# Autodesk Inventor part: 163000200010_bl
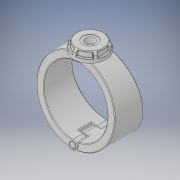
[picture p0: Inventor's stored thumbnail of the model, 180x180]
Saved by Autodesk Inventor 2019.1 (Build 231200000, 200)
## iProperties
Created: 2022-02
Part Number: 163000200010_bl
Material: Generic
Description: Plassadle Threaded 200x1''
Document SubType Name: Modeling
Designer: comp2
Density: 1 g/cm^3
Appearance: Default
Author: comp2
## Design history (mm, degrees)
derived "16300.ipt"
feature "Solid1::16300.ipt" dims "ScaleForDerivedMember" = 10
feature "Solid2::16300.ipt" dims "ScaleForDerivedMember" = 10
feature "Solid3::16300.ipt" dims "ScaleForDerivedMember" = 10
feature "Solid4::16300.ipt" dims "ScaleForDerivedMember" = 10
tag "TaggingFeature1"
body "Solid1"
body "Solid2"
body "Solid3"
body "Solid4"
other parameters: "d2" = 246 [user parameter], "d7" = 233.7 [user parameter], "d8" = 85 deg [user parameter], "d9" = 45 deg [user parameter], "d10" = 102 [user parameter], "d11" = 49 [user parameter], "d12" = 19.061 [user parameter], "d13" = 42.84 [user parameter], "d14" = 45.4365 [user parameter], "d42" = 4.6 [user parameter], "d49" = 4.92 [user parameter], "d50" = 115 [user parameter], "d51" = 0 [user parameter], "d52" = 32.2 [user parameter], "d53" = 135.3 [user parameter], "d54" = 40.25 [user parameter], "d55" = 0 [user parameter], "d56" = 23 [user parameter], "d57" = 23 [user parameter], "d59" = 0 [user parameter], "d60" = 115 [user parameter], "d61" = 0 [user parameter], "d62" = 40.25 [user parameter], "d63" = 0 [user parameter], "d65" = 0 [user parameter], "d67" = 0 [user parameter], "d69" = 0 [user parameter], "d70" = 1 [user parameter], "d71" = 110.4 [user parameter], "d72" = 0 [user parameter], "d73" = 2 [user parameter], "d78" = 86.7 [user parameter], "d79" = 5.1 [user parameter], "d80" = 60 deg [user parameter], "d81" = 5.1 [user parameter], "d84" = 0 [user parameter], "d85" = 1 [user parameter], "d87" = 360 deg [user parameter], "d122" = 49 [user parameter], "d124" = 42.80128 [user parameter], "d125" = 1.3615 [user parameter], "d127" = 272 [user parameter], "d129" = 30.291 [user parameter], "d130" = 25.74735 [user parameter], "d131" = 25.97 [user parameter], "d132" = 45 deg [user parameter], "d133" = 18.179 [user parameter], "d134" = 15.1455 [user parameter], "d136" = 0 [user parameter], "d138" = 0 [user parameter], "d1" = 25 [user parameter], "B" = 246 [user parameter], "L" = 115 [user parameter], "E_" = 54 [user parameter], "E1" = 102 [user parameter], "H1" = 272 [user parameter], "H2" = 49 [user parameter], "H3" = 78 [user parameter], "H_costum" = 49 [user parameter], "Rp" = 30.291 [user parameter], "d128" = 27.23 [user parameter]
